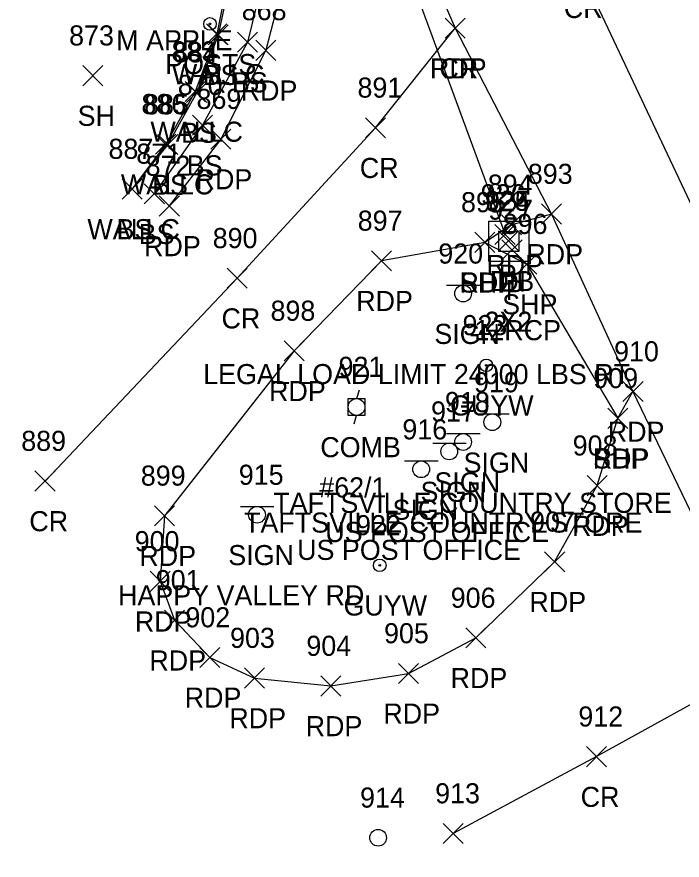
# Model space of a CAD drawing. Extents: x 1647133 to 1649138, y 411736 to 414924.
# Drawn here: x 1648573.3 to 1648639.6, y 412109.7 to 412193.6 of the extents above; entities that cross this region are included whole.
import ezdxf

# ---------------------------------------------------------------- set-up
doc = ezdxf.new("R2010")
doc.units = 0
for name, color, linetype in [('D_A', 7, 'Continuous'), ('D_C', 7, 'Continuous'), ('D_I', 7, 'Continuous'), ('D_TIC', 7, 'Continuous'), ('DCP', 7, 'Continuous'), ('DS', 7, 'Continuous'), ('L_A', 7, 'Continuous'), ('L_C', 7, 'Continuous'), ('L_I', 7, 'Continuous'), ('L_TIC', 7, 'Continuous'), ('LELB', 7, 'Continuous'), ('LPST', 7, 'Continuous'), ('LW', 7, 'Continuous'), ('P_A', 7, 'Continuous'), ('P_I', 7, 'Continuous'), ('P_TIC', 7, 'Continuous'), ('PET', 7, 'Continuous'), ('PRC', 7, 'Continuous'), ('PSP', 7, 'Continuous'), ('S_A', 7, 'Continuous'), ('S_C', 7, 'Continuous'), ('S_I', 7, 'Continuous'), ('SSGN', 7, 'Continuous'), ('U_A', 7, 'Continuous'), ('U_C', 7, 'Continuous'), ('U_I', 7, 'Continuous'), ('UP', 7, 'Continuous'), ('UPGW', 7, 'Continuous'), ('USMH', 7, 'Continuous')]:
    doc.layers.add(name, color=color, linetype=linetype)

msp = doc.modelspace()

# ---------------------------------------------------------------- linework, layer by layer
at = {"layer": 'D_TIC'}
for points in [[(1648620.957, 412170.977), (1648622.957, 412172.977)], [(1648622.957, 412170.977), (1648620.957, 412172.977)], [(1648621.304, 412170.335), (1648623.304, 412172.335)], [(1648623.304, 412170.335), (1648621.304, 412172.335)], [(1648621.65, 412169.451), (1648623.65, 412171.451)], [(1648623.65, 412169.451), (1648621.65, 412171.451)]]:
    msp.add_lwpolyline(points, dxfattribs=at)
at = {"layer": 'DCP'}
msp.add_lwpolyline([(1648599.469, 412233.061), (1648621.957, 412171.977)], dxfattribs=at)
at = {"layer": 'DS'}
for p, q in [((1648620.336, 412173.287), (1648624.336, 412173.287)), ((1648620.336, 412169.287), (1648620.336, 412173.287)), ((1648624.336, 412173.287), (1648624.336, 412169.287)), ((1648621.336, 412170.287), (1648621.336, 412172.287)), ((1648621.336, 412172.287), (1648623.336, 412172.287)), ((1648623.336, 412172.287), (1648623.336, 412170.287)), ((1648622.341, 412171.289), (1648622.341, 412171.289)), ((1648622.341, 412171.289), (1648622.341, 412171.289)), ((1648623.336, 412170.287), (1648621.336, 412170.287)), ((1648624.336, 412169.287), (1648620.336, 412169.287))]:
    msp.add_line(p, q, dxfattribs=at)
at = {"layer": 'L_TIC'}
for points in [[(1648592.244, 412190.936), (1648594.244, 412192.936)], [(1648594.244, 412190.936), (1648592.244, 412192.936)], [(1648592.402, 412190.86), (1648594.402, 412192.86)], [(1648594.402, 412190.86), (1648592.402, 412192.86)], [(1648595.317, 412190.125), (1648597.317, 412192.125)], [(1648597.317, 412190.125), (1648595.317, 412192.125)], [(1648579.908, 412186.792), (1648581.908, 412188.792)], [(1648581.908, 412186.792), (1648579.908, 412188.792)], [(1648590.109, 412185.208), (1648592.109, 412187.208)], [(1648592.109, 412185.208), (1648590.109, 412187.208)], [(1648590.25, 412185.106), (1648592.25, 412187.106)], [(1648592.25, 412185.106), (1648590.25, 412187.106)], [(1648590.817, 412181.862), (1648592.817, 412183.862)], [(1648592.817, 412181.862), (1648590.817, 412183.862)], [(1648587.165, 412179.966), (1648589.165, 412181.966)], [(1648589.165, 412179.966), (1648587.165, 412181.966)], [(1648587.369, 412179.929), (1648589.369, 412181.929)], [(1648589.369, 412179.929), (1648587.369, 412181.929)], [(1648583.83, 412175.507), (1648585.83, 412177.507)], [(1648585.83, 412175.507), (1648583.83, 412177.507)], [(1648583.83, 412175.507), (1648585.83, 412177.507)], [(1648585.83, 412175.507), (1648583.83, 412177.507)], [(1648586.03, 412175.027), (1648588.03, 412177.027)], [(1648588.03, 412175.027), (1648586.03, 412177.027)]]:
    msp.add_lwpolyline(points, dxfattribs=at)
at = {"layer": 'LELB'}
for points in [[(1648528.102, 412316.924), (1648543.223, 412325.481), (1648545.407, 412332.368), (1648562.946, 412299.645), (1648581.792, 412263.745), (1648602.068, 412221.517), (1648598.573, 412200.364), (1648596.317, 412191.125), (1648591.817, 412182.862), (1648587.03, 412176.027)], [(1648529.88, 412310.819), (1648544.703, 412317.882), (1648555.501, 412294.609), (1648571.397, 412258.462), (1648593.938, 412207.246), (1648595.417, 412201.261), (1648593.402, 412191.86), (1648591.25, 412186.106), (1648588.369, 412180.929), (1648584.83, 412176.507)]]:
    msp.add_lwpolyline(points, dxfattribs=at)
at = {"layer": 'LPST'}
for radius in [0.625, 0.0833]:
    msp.add_circle((1648592.575, 412192.941), radius, dxfattribs=at)
at = {"layer": 'LW'}
msp.add_lwpolyline([(1648593.849, 412206.786), (1648595.144, 412201.367), (1648593.244, 412191.936), (1648591.109, 412186.208), (1648588.165, 412180.966), (1648584.83, 412176.507)], dxfattribs=at)
at = {"layer": 'P_TIC'}
for points in [[(1648615.989, 412191.513), (1648617.989, 412193.513)], [(1648617.989, 412191.513), (1648615.989, 412193.513)], [(1648615.989, 412191.513), (1648617.989, 412193.513)], [(1648617.989, 412191.513), (1648615.989, 412193.513)], [(1648597.145, 412189.311), (1648599.145, 412191.311)], [(1648599.145, 412189.311), (1648597.145, 412191.311)], [(1648608.062, 412181.602), (1648610.062, 412183.602)], [(1648610.062, 412181.602), (1648608.062, 412183.602)], [(1648592.652, 412180.477), (1648594.652, 412182.477)], [(1648594.652, 412180.477), (1648592.652, 412182.477)], [(1648587.525, 412173.816), (1648589.525, 412175.816)], [(1648589.525, 412173.816), (1648587.525, 412175.816)], [(1648625.592, 412173.015), (1648627.592, 412175.015)], [(1648627.592, 412173.015), (1648625.592, 412175.015)], [(1648625.592, 412173.015), (1648627.592, 412175.015)], [(1648627.592, 412173.015), (1648625.592, 412175.015)], [(1648621.605, 412171.939), (1648623.605, 412173.939)], [(1648623.605, 412171.939), (1648621.605, 412173.939)], [(1648618.937, 412170.193), (1648620.937, 412172.193)], [(1648620.937, 412170.193), (1648618.937, 412172.193)], [(1648618.937, 412170.193), (1648620.937, 412172.193)], [(1648620.937, 412170.193), (1648618.937, 412172.193)], [(1648608.65, 412168.357), (1648610.65, 412170.357)], [(1648610.65, 412168.357), (1648608.65, 412170.357)], [(1648623.138, 412168.027), (1648625.138, 412170.027)], [(1648625.138, 412168.027), (1648623.138, 412170.027)], [(1648594.292, 412166.621), (1648596.292, 412168.621)], [(1648596.292, 412166.621), (1648594.292, 412168.621)], [(1648599.969, 412159.386), (1648601.969, 412161.386)], [(1648601.969, 412159.386), (1648599.969, 412161.386)], [(1648633.702, 412155.346), (1648635.702, 412157.346)], [(1648635.702, 412155.346), (1648633.702, 412157.346)], [(1648633.702, 412155.346), (1648635.702, 412157.346)], [(1648635.702, 412155.346), (1648633.702, 412157.346)], [(1648632.199, 412152.678), (1648634.199, 412154.678)], [(1648634.199, 412152.678), (1648632.199, 412154.678)], [(1648632.199, 412152.678), (1648634.199, 412154.678)], [(1648634.199, 412152.678), (1648632.199, 412154.678)], [(1648575.148, 412146.433), (1648577.148, 412148.433)], [(1648577.148, 412146.433), (1648575.148, 412148.433)], [(1648630.136, 412145.972), (1648632.136, 412147.972)], [(1648632.136, 412145.972), (1648630.136, 412147.972)], [(1648587.055, 412142.974), (1648589.055, 412144.974)], [(1648589.055, 412142.974), (1648587.055, 412144.974)], [(1648625.898, 412138.397), (1648627.898, 412140.397)], [(1648627.898, 412138.397), (1648625.898, 412140.397)], [(1648586.602, 412136.448), (1648588.602, 412138.448)], [(1648588.602, 412136.448), (1648586.602, 412138.448)], [(1648588.051, 412132.567), (1648590.051, 412134.567)], [(1648590.051, 412132.567), (1648588.051, 412134.567)], [(1648618.047, 412130.814), (1648620.047, 412132.814)], [(1648620.047, 412130.814), (1648618.047, 412132.814)], [(1648591.566, 412128.868), (1648593.566, 412130.868)], [(1648593.566, 412128.868), (1648591.566, 412130.868)], [(1648596.014, 412126.819), (1648598.014, 412128.819)], [(1648598.014, 412126.819), (1648596.014, 412128.819)], [(1648611.35, 412127.281), (1648613.35, 412129.281)], [(1648613.35, 412127.281), (1648611.35, 412129.281)], [(1648603.616, 412126.028), (1648605.616, 412128.028)], [(1648605.616, 412126.028), (1648603.616, 412128.028)], [(1648630.056, 412118.991), (1648632.056, 412120.991)], [(1648632.056, 412118.991), (1648630.056, 412120.991)], [(1648615.796, 412111.345), (1648617.796, 412113.345)], [(1648617.796, 412111.345), (1648615.796, 412113.345)]]:
    msp.add_lwpolyline(points, dxfattribs=at)
at = {"layer": 'PET'}
for points in [[(1648512.544, 412422.792), (1648530.09, 412384.206), (1648549.578, 412341.858), (1648567.717, 412302.186), (1648584.888, 412264.911), (1648603.961, 412222.556), (1648616.989, 412192.513), (1648626.592, 412174.015), (1648634.702, 412156.346), (1648647.722, 412129.202), (1648659.195, 412106.441), (1648667.013, 412092.615), (1648674.657, 412079.411), (1648685.658, 412062.516), (1648700.073, 412044.859), (1648717.467, 412025.769), (1648741.246, 412001.123), (1648755.318, 411988.116), (1648772.85, 411971.957)], [(1648603.961, 412222.556), (1648602.143, 412208.248), (1648600.367, 412198.957), (1648598.145, 412190.311), (1648593.652, 412181.477), (1648588.525, 412174.816)], [(1648626.592, 412174.015), (1648622.605, 412172.939), (1648619.937, 412171.193), (1648609.65, 412169.357), (1648600.969, 412160.386), (1648588.055, 412143.974), (1648587.602, 412137.448), (1648589.051, 412133.567), (1648592.566, 412129.868), (1648597.014, 412127.819), (1648604.616, 412127.028), (1648612.35, 412128.281), (1648619.047, 412131.814), (1648626.898, 412139.397), (1648631.136, 412146.972), (1648633.199, 412153.678), (1648634.702, 412156.346)]]:
    msp.add_lwpolyline(points, dxfattribs=at)
at = {"layer": 'PRC'}
for points in [[(1648523.855, 412428.164), (1648541.762, 412388.819), (1648560.786, 412347.218), (1648578.952, 412307.656), (1648596.522, 412268.849), (1648615.514, 412228.06), (1648629.383, 412198.525), (1648645.407, 412164.541), (1648659.578, 412134.14), (1648672.041, 412110.748), (1648683.898, 412091.11), (1648700.383, 412068.335), (1648715.839, 412049.98), (1648739.601, 412024.905), (1648761.868, 412004.355), (1648787.636, 411981.064), (1648820.993, 411950.624), (1648837.381, 411936.249), (1648865.129, 411910.894), (1648893.845, 411885.618), (1648930.35, 411852.903), (1648951.421, 411834.103), (1648988.1, 411800.425), (1649025.041, 411766.663)], [(1648576.148, 412147.433), (1648595.292, 412167.621), (1648609.062, 412182.602), (1648616.989, 412192.513)], [(1648647.722, 412129.202), (1648631.056, 412119.991), (1648616.796, 412112.345)]]:
    msp.add_lwpolyline(points, dxfattribs=at)
at = {"layer": 'PSP'}
msp.add_lwpolyline([(1648619.937, 412171.193), (1648624.138, 412169.027), (1648633.199, 412153.678)], dxfattribs=at)
at = {"layer": 'SSGN'}
for p, q in [((1648616.134, 412166.932), (1648619.467, 412166.932)), ((1648617.781, 412166.098), (1648617.781, 412166.098)), ((1648619.046, 412154.118), (1648622.379, 412154.118)), ((1648620.692, 412153.284), (1648620.692, 412153.284)), ((1648616.139, 412152.152), (1648619.472, 412152.152)), ((1648614.757, 412151.212), (1648618.09, 412151.212)), ((1648617.786, 412151.319), (1648617.786, 412151.319)), ((1648616.403, 412150.378), (1648616.403, 412150.378)), ((1648611.961, 412149.433), (1648615.294, 412149.433)), ((1648613.608, 412148.6), (1648613.608, 412148.6)), ((1648595.611, 412144.91), (1648598.944, 412144.91)), ((1648597.258, 412144.077), (1648597.258, 412144.077))]:
    msp.add_line(p, q, dxfattribs=at)
for centre in [(1648617.781, 412166.098), (1648620.692, 412153.284), (1648617.786, 412151.319), (1648616.403, 412150.378), (1648613.608, 412148.6), (1648597.258, 412144.077)]:
    msp.add_circle(centre, 0.833, dxfattribs=at)
at = {"layer": 'UP'}
for p, q in [((1648607.424, 412156.47), (1648607.174, 412155.636)), ((1648606.341, 412153.97), (1648606.341, 412155.636)), ((1648606.341, 412155.636), (1648608.007, 412155.636)), ((1648608.007, 412155.636), (1648608.007, 412153.97)), ((1648607.174, 412154.803), (1648607.174, 412154.803)), ((1648608.007, 412153.97), (1648606.341, 412153.97)), ((1648606.924, 412153.136), (1648607.174, 412153.97))]:
    msp.add_line(p, q, dxfattribs=at)
msp.add_circle((1648607.174, 412154.803), 0.833, dxfattribs=at)
at = {"layer": 'UPGW'}
for centre, radius in [((1648620.088, 412158.954), 0.625), ((1648620.088, 412158.954), 0.0833), ((1648609.481, 412139.039), 0.625), ((1648609.481, 412139.039), 0.0833)]:
    msp.add_circle(centre, radius, dxfattribs=at)
at = {"layer": 'USMH'}
for p, q in [((1648609.317, 412111.92), (1648609.317, 412111.92)), ((1648610.15, 412111.92), (1648610.15, 412111.92))]:
    msp.add_line(p, q, dxfattribs=at)
msp.add_circle((1648609.317, 412111.92), 0.833, dxfattribs=at)

# ---------------------------------------------------------------- texts
at = {"layer": 'D_A'}
for s, p in [('DIB', (1648620.406, 412166.335)), ('P', (1648621.335, 412166.977)), ('DI', (1648621.396, 412166.289)), ('P', (1648622.028, 412165.451))]:
    msp.add_text(s, height=2, dxfattribs=at).set_placement(p)
at = {"layer": 'D_C'}
for s, p in [('2X2', (1648619.916, 412162.289)), ('12RCP', (1648618.91, 412161.451))]:
    msp.add_text(s, height=2, dxfattribs=at).set_placement(p)
at = {"layer": 'D_I'}
for s, p in [('926', (1648619.54, 412174.977)), ('925', (1648619.941, 412174.335)), ('924', (1648619.979, 412174.289)), ('927', (1648620.288, 412173.451))]:
    msp.add_text(s, height=2, dxfattribs=at).set_placement(p)
at = {"layer": 'L_A'}
for s, p in [('POSTS', (1648588.119, 412187.941)), ('WALLC', (1648588.779, 412186.936)), ('BS', (1648591.843, 412186.86)), ('BS', (1648594.758, 412186.125)), ('SH', (1648579.396, 412182.792)), ('WALLC', (1648586.644, 412181.208)), ('BS', (1648589.691, 412181.106)), ('BS', (1648590.258, 412177.862)), ('WALLC', (1648583.7, 412175.966)), ('BS', (1648586.81, 412175.929)), ('WALLC', (1648580.365, 412171.507)), ('BS', (1648583.271, 412171.507)), ('BS', (1648585.471, 412171.027))]:
    msp.add_text(s, height=2, dxfattribs=at).set_placement(p)
at = {"layer": 'L_C'}
msp.add_text('M APPLE', height=2, dxfattribs=at).set_placement((1648583.237, 412190.314))
at = {"layer": 'L_I'}
for s, p in [('873', (1648578.546, 412190.792)), ('883', (1648588.746, 412189.208)), ('884', (1648588.888, 412189.106)), ('870', (1648589.368, 412185.862)), ('886', (1648585.747, 412183.966)), ('885', (1648586.007, 412183.929)), ('887', (1648582.468, 412179.507)), ('887', (1648582.468, 412179.507)), ('871', (1648585.235, 412179.027))]:
    msp.add_text(s, height=2, dxfattribs=at).set_placement(p)
at = {"layer": 'P_A'}
for s, p in [('CR', (1648627.816, 412193.525)), ('RDP', (1648614.477, 412187.513)), ('CR', (1648615.422, 412187.513)), ('RDP', (1648595.633, 412185.311)), ('CR', (1648607.495, 412177.602)), ('RDP', (1648591.14, 412176.477)), ('RDP', (1648586.013, 412169.816)), ('RDP', (1648624.081, 412169.015)), ('RDP', (1648624.081, 412169.015)), ('RDP', (1648620.094, 412167.939)), ('SHP', (1648617.472, 412166.193)), ('RDP', (1648617.425, 412166.193)), ('RDP', (1648607.139, 412164.357)), ('SHP', (1648621.674, 412164.027)), ('CR', (1648593.725, 412162.621)), ('RDP', (1648598.457, 412155.386)), ('RDP', (1648632.19, 412151.346)), ('RDP', (1648632.19, 412151.346)), ('SHP', (1648630.734, 412148.678)), ('RDP', (1648630.687, 412148.678)), ('CR', (1648574.581, 412142.433)), ('RDP', (1648628.624, 412141.972)), ('RDP', (1648585.543, 412138.974)), ('RDP', (1648624.386, 412134.397)), ('RDP', (1648585.09, 412132.448)), ('RDP', (1648586.539, 412128.567)), ('RDP', (1648616.536, 412126.814)), ('RDP', (1648590.054, 412124.868)), ('RDP', (1648594.502, 412122.819)), ('RDP', (1648609.838, 412123.281)), ('RDP', (1648602.104, 412122.028)), ('CR', (1648629.489, 412114.991))]:
    msp.add_text(s, height=2, dxfattribs=at).set_placement(p)
at = {"layer": 'P_I'}
for s, p in [('868', (1648595.735, 412193.311)), ('891', (1648607.266, 412185.602)), ('869', (1648591.235, 412184.477)), ('872', (1648586.163, 412177.816)), ('893', (1648624.23, 412177.015)), ('893', (1648624.23, 412177.015)), ('894', (1648620.243, 412175.939)), ('895', (1648617.575, 412174.193)), ('895', (1648617.575, 412174.193)), ('897', (1648607.288, 412172.357)), ('896', (1648621.721, 412172.027)), ('890', (1648592.844, 412170.621)), ('898', (1648598.606, 412163.386)), ('910', (1648632.82, 412159.346)), ('910', (1648632.82, 412159.346)), ('909', (1648630.75, 412156.678)), ('909', (1648630.75, 412156.678)), ('889', (1648573.778, 412150.433)), ('908', (1648628.695, 412149.972)), ('899', (1648585.685, 412146.974)), ('907', (1648624.457, 412142.397)), ('900', (1648585.075, 412140.448)), ('901', (1648587.177, 412136.567)), ('906', (1648616.551, 412134.814)), ('902', (1648590.125, 412132.868)), ('905', (1648609.909, 412131.281)), ('903', (1648594.573, 412130.819)), ('904', (1648602.175, 412130.028)), ('912', (1648629.26, 412122.991)), ('913', (1648615.001, 412115.345))]:
    msp.add_text(s, height=2, dxfattribs=at).set_placement(p)
at = {"layer": 'S_A'}
for p in [(1648614.919, 412161.078), (1648617.83, 412148.264), (1648614.924, 412146.298), (1648613.541, 412145.358), (1648610.746, 412143.579), (1648594.396, 412139.057)]:
    msp.add_text('SIGN', height=2, dxfattribs=at).set_placement(p)
at = {"layer": 'S_C'}
for s, p in [('LEGAL LOAD LIMIT 24000 LBS RT', (1648591.895, 412157.078)), ('TAFTSVILLE COUNTRY STORE', (1648598.878, 412144.264)), ('TAFTSVILLE COUNTRY STORE', (1648595.971, 412142.298)), ('US POST OFFICE', (1648604.053, 412141.358)), ('US POST OFFICE', (1648601.257, 412139.579)), ('HAPPY VALLEY RD', (1648583.419, 412135.057))]:
    msp.add_text(s, height=2, dxfattribs=at).set_placement(p)
at = {"layer": 'S_I'}
for s, p in [('920', (1648615.312, 412169.078)), ('919', (1648618.87, 412156.264)), ('918', (1648615.971, 412154.298)), ('917', (1648614.589, 412153.358)), ('916', (1648611.738, 412151.579)), ('915', (1648595.443, 412147.057))]:
    msp.add_text(s, height=2, dxfattribs=at).set_placement(p)
at = {"layer": 'U_A'}
for s, p in [('GUYW', (1648616.481, 412153.954)), ('COMB', (1648603.56, 412149.803)), ('GUYW', (1648605.875, 412134.039))]:
    msp.add_text(s, height=2, dxfattribs=at).set_placement(p)
at = {"layer": 'U_C'}
msp.add_text('#62/1', height=2, dxfattribs=at).set_placement((1648603.457, 412145.803))
at = {"layer": 'U_I'}
for s, p in [('923', (1648617.726, 412161.954)), ('921', (1648605.379, 412157.803)), ('922', (1648607.119, 412142.039)), ('914', (1648607.521, 412114.92))]:
    msp.add_text(s, height=2, dxfattribs=at).set_placement(p)

doc.saveas('drawing.dxf')
